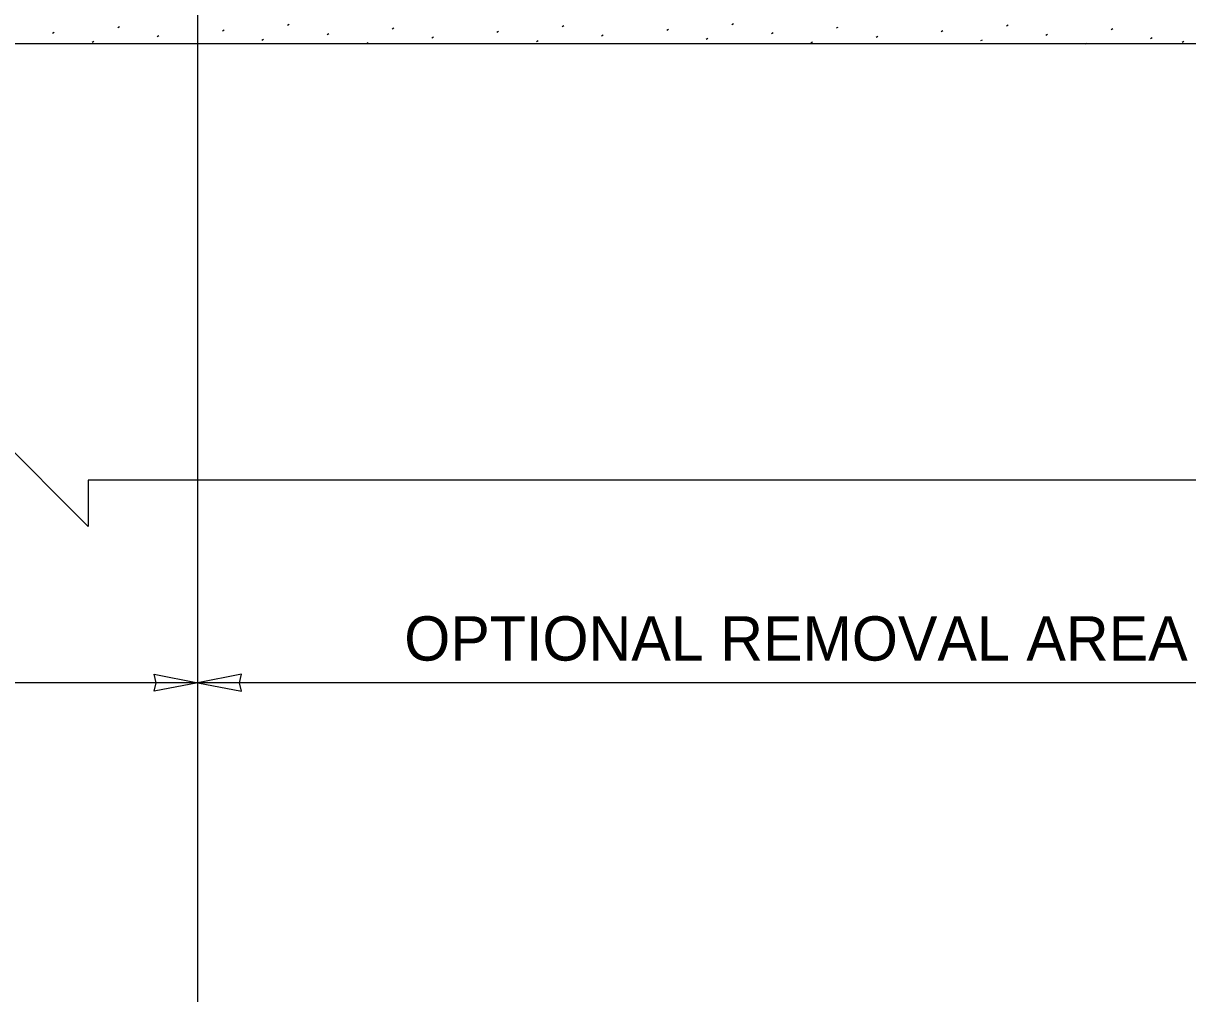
# Model space of a CAD drawing. Extents: x 99862 to 104211, y 98939 to 105076.
# Drawn here: x 101994.4 to 102415, y 104381.5 to 104731.9 of the extents above; entities that cross this region are included whole.
import ezdxf

# ---------------------------------------------------------------- set-up
doc = ezdxf.new("R2010")
doc.units = 0
for name, color, linetype in [('Level 1', 7, 'Continuous'), ('Level 15', 7, 'Continuous'), ('Level 20', 7, 'Continuous'), ('Level 3', 7, 'Continuous')]:
    doc.layers.add(name, color=color, linetype=linetype)

msp = doc.modelspace()

# ---------------------------------------------------------------- linework, layer by layer
at = {"layer": 'Level 1'}
msp.add_line((102495.44, 104724.41), (100264.63, 104724.41), dxfattribs=at)
msp.add_lwpolyline([(102651.95, 104566.9), (102017.87, 104566.9), (102017.87, 104550.19), (101984.46, 104583.6), (101984.46, 104566.9), (101386.54, 104566.9)], dxfattribs=at)
at = {"layer": 'Level 15'}
for p, q in [((102057.49, 104724.41), (102057.47, 104882.79)), ((102057.49, 104263.53), (102057.49, 104724.41)), ((102057.49, 104493.74), (100698.76, 104493.74)), ((102495.51, 104493.74), (102057.49, 104493.74))]:
    msp.add_line(p, q, dxfattribs=at)
for points in [[(102057.49, 104493.74), (102041.76, 104490.66), (102042.49, 104493.74), (102041.76, 104496.83)], [(102057.49, 104493.74), (102073.21, 104490.66), (102072.48, 104493.74), (102073.21, 104496.83)]]:
    msp.add_lwpolyline(points, close=True, dxfattribs=at)
at = {"layer": 'Level 3'}
for p, q in [((102005.04, 104728.34), (102005.65, 104728.69)), ((102028.58, 104730.39), (102029.18, 104730.74)), ((102066.38, 104729.12), (102066.98, 104729.47)), ((102089.91, 104731.16), (102090.52, 104731.51)), ((102127.72, 104729.89), (102128.32, 104730.24)), ((102165.52, 104728.62), (102166.13, 104728.97)), ((102189.06, 104730.66), (102189.66, 104731.01)), ((102226.86, 104729.39), (102227.46, 104729.74)), ((102250.39, 104731.44), (102251, 104731.79)), ((102264.66, 104728.13), (102265.27, 104728.48)), ((102288.2, 104730.17), (102288.8, 104730.52)), ((102326, 104728.9), (102326.61, 104729.25)), ((102349.54, 104730.94), (102350.14, 104731.29)), ((102387.34, 104729.67), (102387.94, 104730.02)), ((102019.31, 104725.03), (102019.91, 104725.38)), ((102042.84, 104727.08), (102043.45, 104727.43)), ((102080.65, 104725.81), (102081.25, 104726.16)), ((102104.18, 104727.85), (102104.79, 104728.2)), ((102118.45, 104724.54), (102119.06, 104724.89)), ((102141.98, 104726.58), (102142.59, 104726.93)), ((102179.79, 104725.31), (102180.39, 104725.66)), ((102203.32, 104727.35), (102203.93, 104727.7)), ((102241.13, 104726.08), (102241.73, 104726.43)), ((102278.93, 104724.82), (102279.54, 104725.17)), ((102302.46, 104726.86), (102303.07, 104727.21)), ((102340.27, 104725.59), (102340.87, 104725.94)), ((102363.8, 104727.63), (102364.41, 104727.98)), ((102378.23, 104724.41), (102378.68, 104724.67)), ((102401.61, 104726.36), (102402.21, 104726.71)), ((102413, 104725.09), (102413.61, 104725.44))]:
    msp.add_line(p, q, dxfattribs=at)

# ---------------------------------------------------------------- texts
at = {"layer": 'Level 20'}
msp.add_text('OPTIONAL REMOVAL AREA', height=16, dxfattribs=at).set_placement((102132.04, 104501.74))

doc.saveas('drawing.dxf')
